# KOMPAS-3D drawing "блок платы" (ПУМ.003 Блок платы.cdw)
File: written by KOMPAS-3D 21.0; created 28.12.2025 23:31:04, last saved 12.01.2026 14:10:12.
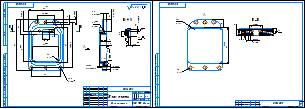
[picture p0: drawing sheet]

Sheets 1-2: A4x2, landscape

Document properties: Полное имя файла: ..\ПУМ.003 Блок платы.m3d; Автор: User; Знак неуказанной шероховатости: 4; Параметр неуказанной шероховатости: Ra 3.2; Масса: 0.031082; Форматы листов документа: 2xA4@4~2

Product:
- Part/product: блок платы
    Материал: Фторопласт-4  ГОСТ 10007-80 Е (density 2200 kg/m3)
    Масса: 0.031082
    Форматы листов документа: 2xA4@4~2
  - Body: Тело 6
      Масса: 0.03115
  - Body: Тело 1
      Масса: 0.03115

Title block, sheet 1: Наименование: Блок платы; designation: ПУМ.003; Материал: Полиацеталь; Масса: 0,03; sheet number: 1; Количество листов документа: 2; organisation: ООО ТПК Пегас; Форматы листов документа: A4 2; stored path: C:\Users\User\Desktop\ПУ\ПУМ\Чертежи\ПУМ.003 Блок платы.cdw; Разработал: Гайсин
Title block, sheet 2: sheet number: 2

Views: Вид 1, Сверху, Проекционный вид 2, Местный разрез 1, Разрез В-В, Вид по стрелке А, Выносной элемент 5, Выносной элемент Б, Выносной элемент
Referenced files in C:\Users\Гузель\Desktop\ПУМ\: ПУМ.003 Блок платы.m3d
Referenced files in C:\Users\User\Desktop\ПУ\ПУМ\: ПУМ.003 Блок платы.m3d
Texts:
  блок платы
  по контуру
  Ra 3.2
  Ra 3.2 ( )
Dimensions and other numbers on the sheet: 70; 48; 24±0,1; 3,5±0,1; 63±0,1; 16±0,1; 40; 5,2; 4 отв; 20; 38; 36; 7; 49; 4; 4 рад; 10; 2 места; 8; 9,5; -7Н; 5; 2 отв; 3; 0,5; 1,6; 8,5; 2; 18±0,1; 11; 50; 2 рад; 1,85; 1,5; 2:1; 0,03; 1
